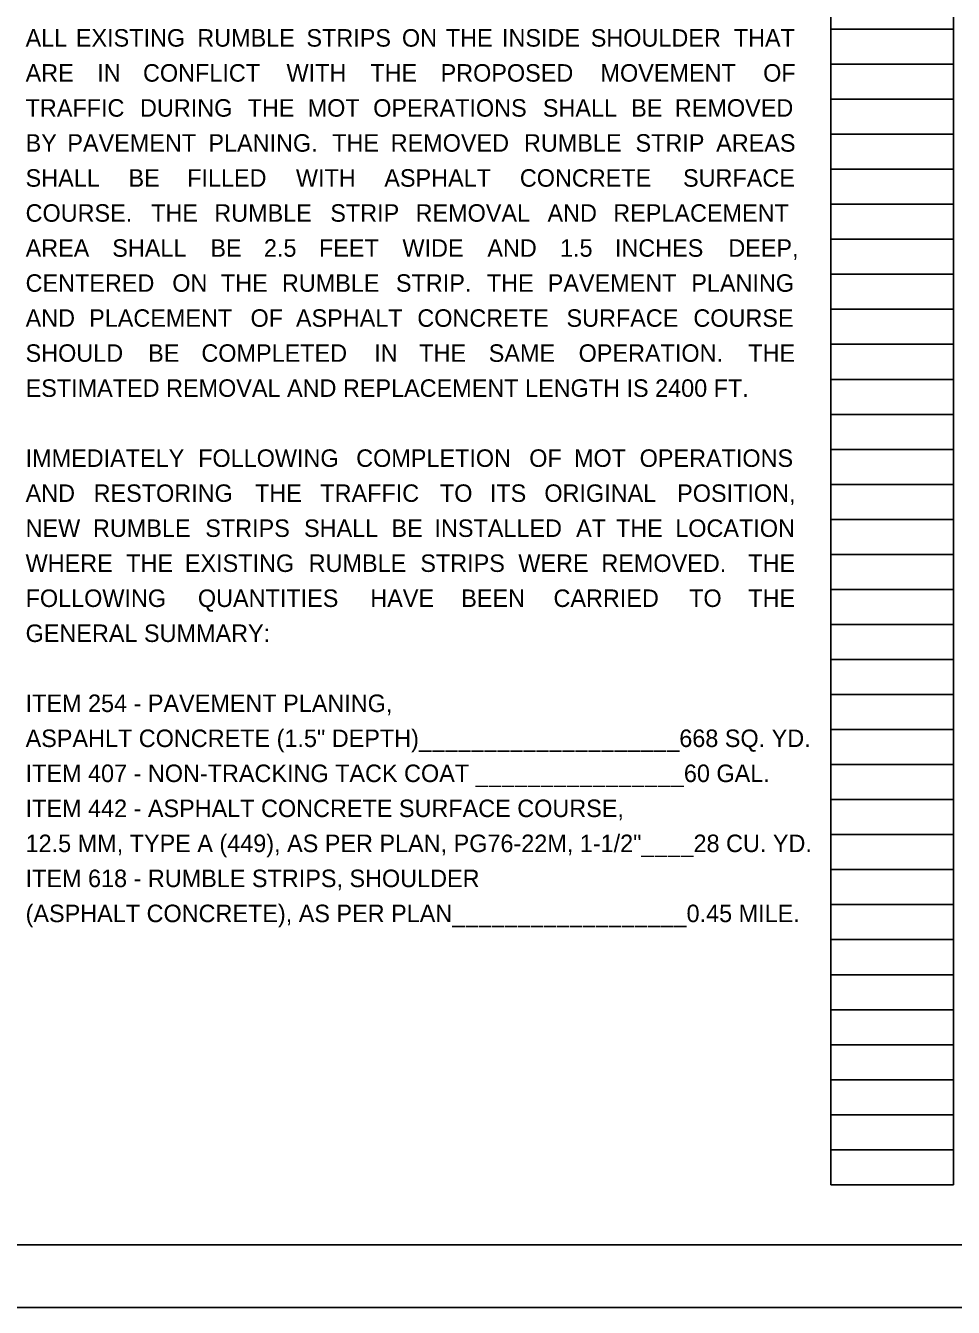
# Model space of a CAD drawing. Extents: x 0 to 34, y 0 to 22.
# Drawn here: x 17.24 to 24.66, y 0 to 10.25 of the extents above; entities that cross this region are included whole.
import ezdxf

# ---------------------------------------------------------------- set-up
doc = ezdxf.new("R2010")
doc.units = 0
for name, color, linetype in [('Default', 7, 'Continuous'), ('SH_Border', 7, 'Continuous'), ('SH_Cut_Line', 7, 'Continuous'), ('SH_Data', 7, 'Continuous'), ('SH_Text', 7, 'Continuous')]:
    doc.layers.add(name, color=color, linetype=linetype)

msp = doc.modelspace()

# ---------------------------------------------------------------- linework, layer by layer
at = {"layer": 'SH_Border'}
msp.add_lwpolyline([(1.5, 21.5), (33.5, 21.5), (33.5, 0.5), (1.5, 0.5)], close=True, dxfattribs=at)
at = {"layer": 'SH_Cut_Line'}
msp.add_lwpolyline([(0, 0), (34, 0), (34, 22), (0, 22)], close=True, dxfattribs=at)
at = {"layer": 'SH_Data'}
for p, q in [((23.68, 0.98), (23.68, 21.14)), ((24.66, 0.98), (24.66, 21.14)), ((23.68, 10.22), (24.66, 10.22)), ((23.68, 9.94), (24.66, 9.94)), ((23.68, 9.66), (24.66, 9.66)), ((23.68, 9.38), (24.66, 9.38)), ((23.68, 9.1), (24.66, 9.1)), ((23.68, 8.82), (24.66, 8.82)), ((23.68, 8.54), (24.66, 8.54)), ((23.68, 8.26), (24.66, 8.26)), ((23.68, 7.98), (24.66, 7.98)), ((23.68, 7.7), (24.66, 7.7)), ((23.68, 7.42), (24.66, 7.42)), ((23.68, 7.14), (24.66, 7.14)), ((23.68, 6.86), (24.66, 6.86)), ((23.68, 6.58), (24.66, 6.58)), ((23.68, 6.3), (24.66, 6.3)), ((23.68, 6.02), (24.66, 6.02)), ((23.68, 5.74), (24.66, 5.74)), ((23.68, 5.46), (24.66, 5.46)), ((23.68, 5.18), (24.66, 5.18)), ((23.68, 4.9), (24.66, 4.9)), ((23.68, 4.62), (24.66, 4.62)), ((23.68, 4.34), (24.66, 4.34)), ((23.68, 4.06), (24.66, 4.06)), ((23.68, 3.78), (24.66, 3.78)), ((23.68, 3.5), (24.66, 3.5)), ((23.68, 3.22), (24.66, 3.22)), ((23.68, 2.94), (24.66, 2.94)), ((23.68, 2.66), (24.66, 2.66)), ((23.68, 2.38), (24.66, 2.38)), ((23.68, 2.1), (24.66, 2.1)), ((23.68, 1.82), (24.66, 1.82)), ((23.68, 1.54), (24.66, 1.54)), ((23.68, 1.26), (24.66, 1.26)), ((23.68, 0.98), (24.66, 0.98))]:
    msp.add_line(p, q, dxfattribs=at)

# ---------------------------------------------------------------- texts
at = {"layer": 'Default'}
for s, p in [('ITEM 254 - PAVEMENT PLANING, ', (17.24, 4.76)), ('ASPAHLT CONCRETE (1.5" DEPTH)____________________668 SQ. YD.', (17.24, 4.48)), ('ITEM 407 - NON-TRACKING TACK COAT ________________60 GAL.', (17.24, 4.2)), ('ITEM 442 - ASPHALT CONCRETE SURFACE COURSE, ', (17.24, 3.92)), ('12.5 MM, TYPE A (449), AS PER PLAN, PG76-22M, 1-1/2"____28 CU. YD.', (17.24, 3.64)), ('ITEM 618 - RUMBLE STRIPS, SHOULDER', (17.24, 3.36)), ('(ASPHALT CONCRETE), AS PER PLAN__________________0.45 MILE.', (17.24, 3.08))]:
    msp.add_text(s, height=0.14, dxfattribs=at).set_placement(p)
at = {"layer": 'SH_Text'}
for s, p in [('ALL ', (17.24, 10.08)), ('EXISTING ', (17.642, 10.08)), ('RUMBLE ', (18.613, 10.08)), ('STRIPS ', (19.486, 10.08)), ('ON ', (20.25, 10.08)), ('THE ', (20.601, 10.08)), ('INSIDE ', (21.05, 10.08)), ('SHOULDER ', (21.76, 10.08)), ('THAT ', (22.904, 10.08)), ('CONFLICT ', (18.179, 9.8)), ('PROPOSED ', (20.559, 9.8)), ('MOVEMENT ', (21.838, 9.8)), ('OF ', (23.139, 9.8)), ('ARE ', (17.24, 9.8)), ('IN ', (17.813, 9.8)), ('WITH ', (19.327, 9.8)), ('THE ', (19.997, 9.8)), ('TRAFFIC ', (17.24, 9.52)), ('DURING ', (18.155, 9.52)), ('THE ', (19.016, 9.52)), ('MOT ', (19.496, 9.52)), ('OPERATIONS ', (20.02, 9.52)), ('SHALL ', (21.377, 9.52)), ('BE ', (22.083, 9.52)), ('REMOVED ', (22.433, 9.52)), ('BY ', (17.24, 9.24)), ('PAVEMENT ', (17.574, 9.24)), ('PLANING. ', (18.702, 9.24)), ('THE ', (19.692, 9.24)), ('REMOVED ', (20.16, 9.24)), ('RUMBLE ', (21.226, 9.24)), ('STRIP ', (22.118, 9.24)), ('AREAS ', (22.763, 9.24)), ('SHALL ', (17.24, 8.96)), ('BE ', (18.063, 8.96)), ('FILLED ', (18.532, 8.96)), ('WITH ', (19.402, 8.96)), ('ASPHALT ', (20.109, 8.96)), ('CONCRETE ', (21.193, 8.96)), ('SURFACE ', (22.498, 8.96)), ('COURSE. ', (17.24, 8.68)), ('THE ', (18.244, 8.68)), ('RUMBLE ', (18.749, 8.68)), ('STRIP ', (19.677, 8.68)), ('REMOVAL ', (20.359, 8.68)), ('AND ', (21.414, 8.68)), ('REPLACEMENT ', (21.94, 8.68)), ('AREA ', (17.24, 8.4)), ('SHALL ', (17.933, 8.4)), ('BE ', (18.718, 8.4)), ('2.5 ', (19.146, 8.4)), ('FEET ', (19.586, 8.4)), ('WIDE ', (20.254, 8.4)), ('AND ', (20.933, 8.4)), ('1.5 ', (21.514, 8.4)), ('INCHES ', (21.953, 8.4)), ('DEEP, ', (22.86, 8.4)), ('CENTERED ', (17.24, 8.12)), ('ON ', (18.413, 8.12)), ('THE ', (18.802, 8.12)), ('RUMBLE ', (19.29, 8.12)), ('STRIP. ', (20.202, 8.12)), ('THE ', (20.929, 8.12)), ('PAVEMENT ', (21.416, 8.12)), ('PLANING ', (22.564, 8.12)), ('AND ', (17.24, 7.84)), ('PLACEMENT ', (17.748, 7.84)), ('OF ', (19.039, 7.84)), ('ASPHALT ', (19.402, 7.84)), ('CONCRETE ', (20.373, 7.84)), ('SURFACE ', (21.566, 7.84)), ('COURSE ', (22.581, 7.84)), ('SHOULD ', (17.24, 7.56)), ('BE ', (18.22, 7.56)), ('COMPLETED ', (18.646, 7.56)), ('IN ', (20.028, 7.56)), ('THE ', (20.388, 7.56)), ('SAME ', (20.944, 7.56)), ('OPERATION. ', (21.663, 7.56)), ('THE ', (23.02, 7.56)), ('ESTIMATED REMOVAL AND REPLACEMENT LENGTH IS 2400 FT.', (17.24, 7.28)), ('IMMEDIATELY ', (17.24, 6.72)), ('FOLLOWING ', (18.62, 6.72)), ('COMPLETION ', (19.884, 6.72)), ('OF ', (21.268, 6.72)), ('MOT ', (21.626, 6.72)), ('OPERATIONS ', (22.151, 6.72)), ('AND ', (17.24, 6.44)), ('RESTORING ', (17.784, 6.44)), ('THE ', (19.075, 6.44)), ('TRAFFIC ', (19.597, 6.44)), ('TO ', (20.554, 6.44)), ('ITS ', (20.953, 6.44)), ('ORIGINAL ', (21.389, 6.44)), ('POSITION, ', (22.451, 6.44)), ('NEW ', (17.24, 6.16)), ('RUMBLE ', (17.779, 6.16)), ('STRIPS ', (18.677, 6.16)), ('SHALL ', (19.467, 6.16)), ('BE ', (20.166, 6.16)), ('INSTALLED ', (20.51, 6.16)), ('AT ', (21.643, 6.16)), ('THE ', (21.962, 6.16)), ('LOCATION ', (22.436, 6.16)), ('WHERE ', (17.24, 5.88)), ('THE ', (18.045, 5.88)), ('EXISTING ', (18.514, 5.88)), ('RUMBLE ', (19.504, 5.88)), ('STRIPS ', (20.397, 5.88)), ('WERE ', (21.181, 5.88)), ('REMOVED.  ', (21.845, 5.88)), ('THE ', (23.02, 5.88)), ('FOLLOWING ', (17.24, 5.6)), ('QUANTITIES ', (18.618, 5.6)), ('HAVE ', (19.997, 5.6)), ('BEEN ', (20.724, 5.6)), ('CARRIED ', (21.462, 5.6)), ('TO ', (22.547, 5.6)), ('THE ', (23.02, 5.6)), ('GENERAL SUMMARY:', (17.24, 5.32))]:
    msp.add_text(s, height=0.14, dxfattribs=at).set_placement(p)

doc.saveas('drawing.dxf')
